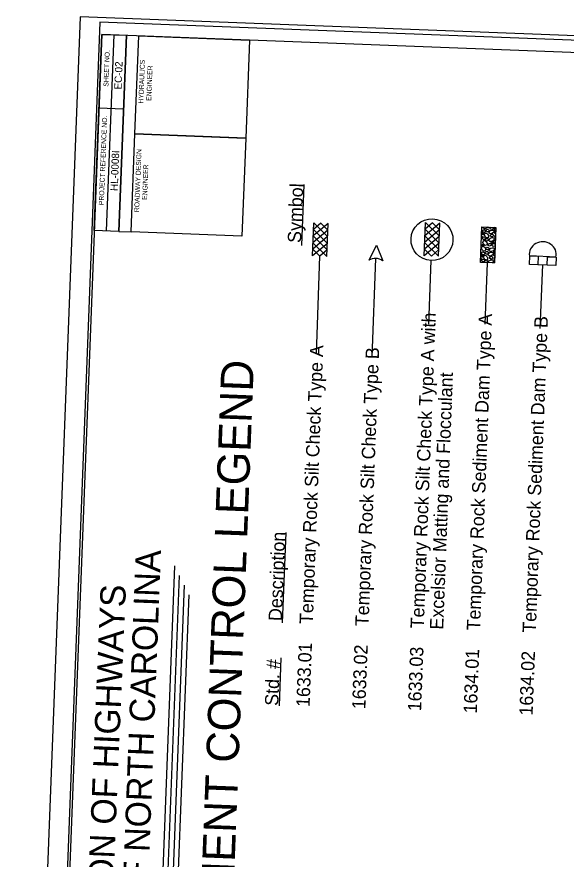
# Model space of a CAD drawing. Extents: x 2094746 to 2100565, y 682095 to 690719.
# Drawn here: x 2094746 to 2097546, y 686425 to 690719 of the extents above; entities that cross this region are included whole.
import ezdxf

# ---------------------------------------------------------------- set-up
doc = ezdxf.new("R2010")
doc.units = 0
for name, color, linetype in [('Default', 7, 'Continuous'), ('Sheet Cutting Line CELL', 7, 'Continuous'), ('Sheet Data Field CELL', 7, 'Continuous'), ('Sheet Plot Border Inside CELL', 7, 'Continuous'), ('Sheet Plot Border Outside CELL', 7, 'Continuous'), ('Sheet Title Data Points CELL', 7, 'Continuous')]:
    doc.layers.add(name, color=color, linetype=linetype)

msp = doc.modelspace()

# ---------------------------------------------------------------- linework, layer by layer
at = {"layer": 'Default'}
for p, q in [((2095471, 685815.7), (2095551.8, 687920.7)), ((2095498.7, 685860.8), (2095575.8, 687871.5)), ((2095527.7, 685905.8), (2095601.3, 687822.3)), ((2095554.1, 685953), (2095623.9, 687773.2))]:
    msp.add_line(p, q, dxfattribs=at)
at = {"layer": 'Sheet Data Field CELL'}
for p, q in [((2095069.1, 690719.1), (2095069.1, 690719.1)), ((2096198.7, 689553.7), (2096210.5, 689864.8)), ((2096252.9, 689500.1), (2096259.3, 689668.8)), ((2096333.1, 689666), (2096256.8, 689602)), ((2096296.2, 689667.4), (2096258, 689634.8)), ((2096259.3, 689668.8), (2096330.4, 689599.2)), ((2096296.2, 689667.4), (2096331.7, 689632)), ((2096326.6, 689497.4), (2096333.1, 689666)), ((2096822.3, 689501.4), (2096828.8, 689670)), ((2096902.4, 689667.3), (2096826.2, 689603.3)), ((2096865.6, 689668.7), (2096827.4, 689636.1)), ((2096828.7, 689670.1), (2096899.8, 689600.5)), ((2096865.6, 689668.7), (2096901.1, 689633.3)), ((2096896, 689498.6), (2096902.4, 689667.3)), ((2096331.7, 689632), (2096255.4, 689566.8)), ((2096258, 689634.8), (2096329.1, 689563.9)), ((2096901.1, 689633.3), (2096824.8, 689568.1)), ((2096827.4, 689636.1), (2096898.5, 689565.2)), ((2096329.1, 689563.9), (2096252.9, 689500.1)), ((2096330.4, 689599.2), (2096254.2, 689534)), ((2096255.4, 689566.8), (2096326.6, 689497.4)), ((2096256.8, 689602), (2096327.9, 689531.3)), ((2096898.5, 689565.2), (2096822.3, 689501.4)), ((2096899.8, 689600.5), (2096823.6, 689535.3)), ((2096824.8, 689568.1), (2096896, 689498.6)), ((2096826.2, 689603.3), (2096897.3, 689532.6)), ((2096254.2, 689534), (2096289.8, 689498.6)), ((2096327.9, 689531.3), (2096289.8, 689498.6)), ((2096541.3, 689478.4), (2096579.8, 689555.5)), ((2096579.8, 689555.5), (2096612.1, 689475.7)), ((2096823.6, 689535.3), (2096859.2, 689499.9)), ((2096897.3, 689532.6), (2096859.2, 689499.9)), ((2096273.4, 689000.2), (2096289.8, 689498.6)), ((2096557.4, 688984.5), (2096576.3, 689487.6)), ((2097495.6, 689494.9), (2097360.9, 689500.1)), ((2097495.6, 689494.9), (2097360.9, 689500.1)), ((2097495.6, 689494.9), (2097493.9, 689451.7)), ((2097495.6, 689494.9), (2097493.9, 689451.7)), ((2096845.8, 689152.9), (2096858.2, 689476.8)), ((2097133.1, 689152.9), (2097144.7, 689465.8)), ((2097493.9, 689451.7), (2097359.3, 689456.9)), ((2097493.9, 689451.7), (2097359.3, 689456.9)), ((2097414.6, 689130.4), (2097426.6, 689454.3)), ((2096100.9, 687629.9), (2096118.5, 688090.3)), ((2096084.6, 687207.1), (2096093.8, 687452.1))]:
    msp.add_line(p, q, dxfattribs=at)
for points in [[(2097109.2, 689466.5), (2097116.2, 689648.4), (2097187.2, 689645.7), (2097180.2, 689465.1)], [(2097109.2, 689466.5), (2097116.2, 689648.4), (2097187.2, 689645.7), (2097180.2, 689465.1)], [(2097359.3, 689456.9), (2097360.9, 689500.1), (2097403.5, 689498.4), (2097401.7, 689455.3)], [(2097449.9, 689453.4), (2097451.6, 689496.6), (2097495.6, 689494.9), (2097493.9, 689451.7)]]:
    msp.add_lwpolyline(points, close=True, dxfattribs=at)
for points in [[(2097115.3, 689622.1), (2097118, 689620.8), (2097117.7, 689614.3), (2097114.8, 689613)], [(2097115.3, 689622.1), (2097118, 689620.8), (2097117.7, 689614.3), (2097114.8, 689613)], [(2097126.5, 689619), (2097121, 689623.2), (2097119.9, 689629.9), (2097124.2, 689633.6), (2097131.3, 689633.3), (2097134, 689629.3), (2097133.7, 689622.9), (2097130.8, 689620.3), (2097126.5, 689619)], [(2097126.5, 689619), (2097121, 689623.2), (2097119.9, 689629.9), (2097124.2, 689633.6), (2097131.3, 689633.3), (2097134, 689629.3), (2097133.7, 689622.9), (2097130.8, 689620.3), (2097126.5, 689619)], [(2097123.2, 689607.5), (2097120.4, 689608.9), (2097120.7, 689612.9), (2097123.5, 689615.4), (2097127.8, 689615.1), (2097129, 689612.5), (2097128.9, 689608.6), (2097127.4, 689607.4), (2097123.2, 689607.5)], [(2097123.2, 689607.5), (2097120.4, 689608.9), (2097120.7, 689612.9), (2097123.5, 689615.4), (2097127.8, 689615.1), (2097129, 689612.5), (2097128.9, 689608.6), (2097127.4, 689607.4), (2097123.2, 689607.5)], [(2097121.8, 689645.4), (2097121.8, 689648.2)], [(2097121.8, 689645.4), (2097121.8, 689648.2)], [(2097138.9, 689647.4), (2097138.7, 689642.2), (2097135.7, 689638.4), (2097130, 689638.6), (2097124.4, 689641.4), (2097121.8, 689645.4)], [(2097138.9, 689647.4), (2097138.7, 689642.2), (2097135.7, 689638.4), (2097130, 689638.6), (2097124.4, 689641.4), (2097121.8, 689645.4)], [(2097132.8, 689599.3), (2097130.3, 689607.3), (2097130.4, 689613.8), (2097134.8, 689616.2), (2097140.5, 689615.9), (2097146, 689611.8), (2097150, 689603.8), (2097149.8, 689597.3), (2097146.7, 689592.1), (2097141, 689592.4), (2097135.5, 689595.2), (2097132.8, 689599.3)], [(2097132.8, 689599.3), (2097130.3, 689607.3), (2097130.4, 689613.8), (2097134.8, 689616.2), (2097140.5, 689615.9), (2097146, 689611.8), (2097150, 689603.8), (2097149.8, 689597.3), (2097146.7, 689592.1), (2097141, 689592.4), (2097135.5, 689595.2), (2097132.8, 689599.3)], [(2097143.6, 689622.4), (2097138.1, 689626.5), (2097138.3, 689633.1), (2097142.8, 689636.9), (2097149.7, 689635.3), (2097152.6, 689632.5), (2097152.3, 689625.9), (2097149.3, 689623.5), (2097143.6, 689622.4)], [(2097143.6, 689622.4), (2097138.1, 689626.5), (2097138.3, 689633.1), (2097142.8, 689636.9), (2097149.7, 689635.3), (2097152.6, 689632.5), (2097152.3, 689625.9), (2097149.3, 689623.5), (2097143.6, 689622.4)], [(2097147.2, 689643.2), (2097141.7, 689647.3)], [(2097147.2, 689643.2), (2097141.7, 689647.3)], [(2097156, 689646.9), (2097156, 689646.9), (2097153, 689644.2), (2097147.2, 689643.2)], [(2097156, 689646.9), (2097156, 689646.9), (2097153, 689644.2), (2097147.2, 689643.2)], [(2097160.9, 689629.5), (2097168, 689631.9), (2097175.3, 689631.6), (2097179.4, 689628.9), (2097177.6, 689623.7), (2097173.3, 689617.3), (2097166, 689613.6), (2097157.5, 689614), (2097153.4, 689616.8), (2097153.6, 689622), (2097156.6, 689627.1), (2097160.9, 689629.5)], [(2097160.9, 689629.5), (2097168, 689631.9), (2097175.3, 689631.6), (2097179.4, 689628.9), (2097177.6, 689623.7), (2097173.3, 689617.3), (2097166, 689613.6), (2097157.5, 689614), (2097153.4, 689616.8), (2097153.6, 689622), (2097156.6, 689627.1), (2097160.9, 689629.5)], [(2097184.3, 689645.8), (2097184.3, 689645.8), (2097178.4, 689639.4), (2097169.7, 689635.9), (2097162.7, 689637.3), (2097158.5, 689640.1), (2097158.7, 689645.4), (2097160.1, 689646.7)], [(2097184.3, 689645.8), (2097184.3, 689645.8), (2097178.4, 689639.4), (2097169.7, 689635.9), (2097162.7, 689637.3), (2097158.5, 689640.1), (2097158.7, 689645.4), (2097160.1, 689646.7)], [(2097166.8, 689597.9), (2097161.3, 689600.7), (2097160.1, 689607.4), (2097165.9, 689611.1), (2097171.5, 689610.9), (2097175.7, 689606.7), (2097174.1, 689601.7), (2097171.1, 689597.8), (2097166.8, 689597.9)], [(2097166.8, 689597.9), (2097161.3, 689600.7), (2097160.1, 689607.4), (2097165.9, 689611.1), (2097171.5, 689610.9), (2097175.7, 689606.7), (2097174.1, 689601.7), (2097171.1, 689597.8), (2097166.8, 689597.9)], [(2097185.8, 689613), (2097181.6, 689615.8), (2097180.5, 689622.3), (2097184.9, 689626.2), (2097186.3, 689626.1)], [(2097185.8, 689613), (2097181.6, 689615.8), (2097180.5, 689622.3), (2097184.9, 689626.2), (2097186.3, 689626.1)], [(2097186.4, 689628.7), (2097182.3, 689631.4), (2097181.1, 689638), (2097186.9, 689641.7), (2097186.9, 689641.7)], [(2097186.4, 689628.7), (2097182.3, 689631.4), (2097181.1, 689638), (2097186.9, 689641.7), (2097186.9, 689641.7)], [(2097114.5, 689602.6), (2097117.3, 689599.8), (2097116.9, 689593.3), (2097114.1, 689592.1)], [(2097114.5, 689602.6), (2097117.3, 689599.8), (2097116.9, 689593.3), (2097114.1, 689592.1)], [(2097125.2, 689583.8), (2097119.6, 689587.9), (2097119.8, 689593.1), (2097124.2, 689598.3), (2097131.3, 689596.6), (2097134, 689592.7), (2097133.8, 689587.4), (2097130.8, 689584.8), (2097125.2, 689583.8)], [(2097125.2, 689583.8), (2097119.6, 689587.9), (2097119.8, 689593.1), (2097124.2, 689598.3), (2097131.3, 689596.6), (2097134, 689592.7), (2097133.8, 689587.4), (2097130.8, 689584.8), (2097125.2, 689583.8)], [(2097124.3, 689560.2), (2097121.6, 689568.2), (2097123.4, 689574.7), (2097126.3, 689578.6), (2097131.9, 689578.3), (2097138.9, 689572.8), (2097142.8, 689564.9), (2097142.6, 689558.2), (2097139.6, 689554.4), (2097133.8, 689553.4), (2097128.4, 689557.5), (2097124.3, 689561.5)], [(2097124.3, 689560.2), (2097121.6, 689568.2), (2097123.4, 689574.7), (2097126.3, 689578.6), (2097131.9, 689578.3), (2097138.9, 689572.8), (2097142.8, 689564.9), (2097142.6, 689558.2), (2097139.6, 689554.4), (2097133.8, 689553.4), (2097128.4, 689557.5), (2097124.3, 689561.5)], [(2097140.4, 689575.3), (2097135, 689580.9), (2097135.1, 689586.1), (2097139.5, 689589.8), (2097146.6, 689589.5), (2097149.3, 689585.4), (2097149.1, 689579.1), (2097146.1, 689576.5), (2097140.4, 689575.3)], [(2097140.4, 689575.3), (2097135, 689580.9), (2097135.1, 689586.1), (2097139.5, 689589.8), (2097146.6, 689589.5), (2097149.3, 689585.4), (2097149.1, 689579.1), (2097146.1, 689576.5), (2097140.4, 689575.3)], [(2097155, 689549.8), (2097149.4, 689554), (2097148.4, 689560.7), (2097154.1, 689564.3), (2097159.8, 689564.1), (2097164, 689560), (2097162.3, 689553.5), (2097159.4, 689551.1), (2097155, 689549.8)], [(2097155, 689549.8), (2097149.4, 689554), (2097148.4, 689560.7), (2097154.1, 689564.3), (2097159.8, 689564.1), (2097164, 689560), (2097162.3, 689553.5), (2097159.4, 689551.1), (2097155, 689549.8)], [(2097160.9, 689591.6), (2097168.1, 689593.9), (2097175.1, 689592.4), (2097179.2, 689589.6), (2097179.1, 689584.4), (2097173.2, 689578.1), (2097164.5, 689574.4), (2097157.4, 689574.7), (2097153.2, 689577.5), (2097153.4, 689582.7), (2097156.5, 689587.9), (2097160.9, 689590.3)], [(2097160.9, 689591.6), (2097168.1, 689593.9), (2097175.1, 689592.4), (2097179.2, 689589.6), (2097179.1, 689584.4), (2097173.2, 689578.1), (2097164.5, 689574.4), (2097157.4, 689574.7), (2097153.2, 689577.5), (2097153.4, 689582.7), (2097156.5, 689587.9), (2097160.9, 689590.3)], [(2097166.9, 689562.6), (2097164.1, 689565.4), (2097164.3, 689569.2), (2097165.8, 689571.7), (2097170.1, 689571.6), (2097172.8, 689568.8), (2097172.7, 689564.9), (2097169.8, 689563.8), (2097166.9, 689562.6)], [(2097166.9, 689562.6), (2097164.1, 689565.4), (2097164.3, 689569.2), (2097165.8, 689571.7), (2097170.1, 689571.6), (2097172.8, 689568.8), (2097172.7, 689564.9), (2097169.8, 689563.8), (2097166.9, 689562.6)], [(2097174.9, 689549.2), (2097169.4, 689553.3), (2097169.6, 689558.5), (2097174, 689563.7), (2097181, 689562.1), (2097183.8, 689558.1)], [(2097174.9, 689549.2), (2097169.4, 689553.3), (2097169.6, 689558.5), (2097174, 689563.7), (2097181, 689562.1), (2097183.8, 689558.1)], [(2097182.4, 689564.6), (2097175.6, 689568.8), (2097175.9, 689575.2), (2097180.2, 689579.1), (2097184.5, 689579)], [(2097182.4, 689564.6), (2097175.6, 689568.8), (2097175.9, 689575.2), (2097180.2, 689579.1), (2097184.5, 689579)], [(2097185.2, 689593.2), (2097182.4, 689597.4), (2097184.1, 689605.1), (2097185.4, 689605)], [(2097185.2, 689593.2), (2097182.4, 689597.4), (2097184.1, 689605.1), (2097185.4, 689605)], [(2097184, 689564.4), (2097182.4, 689564.6)], [(2097184, 689564.4), (2097182.4, 689564.6)], [(2097112.3, 689543.7), (2097113.6, 689543.7), (2097113.3, 689537.1), (2097112, 689537.1)], [(2097112.3, 689543.7), (2097113.6, 689543.7), (2097113.3, 689537.1), (2097112, 689537.1)], [(2097117.5, 689533.1), (2097114.9, 689539.6), (2097115.2, 689546.2), (2097119.5, 689548.6), (2097125.2, 689548.4), (2097132.1, 689544.2), (2097134.6, 689536.3), (2097134.4, 689529.8), (2097131.4, 689526), (2097125.7, 689524.8), (2097120.2, 689528.9), (2097117.5, 689533.1)], [(2097117.5, 689533.1), (2097114.9, 689539.6), (2097115.2, 689546.2), (2097119.5, 689548.6), (2097125.2, 689548.4), (2097132.1, 689544.2), (2097134.6, 689536.3), (2097134.4, 689529.8), (2097131.4, 689526), (2097125.7, 689524.8), (2097120.2, 689528.9), (2097117.5, 689533.1)], [(2097122.2, 689506.5), (2097116.6, 689510.8), (2097115.5, 689517.3), (2097119.9, 689521.2), (2097126.9, 689519.5), (2097131.1, 689515.5), (2097129.3, 689510.2), (2097126.4, 689506.5), (2097122.2, 689506.5)], [(2097122.2, 689506.5), (2097116.6, 689510.8), (2097115.5, 689517.3), (2097119.9, 689521.2), (2097126.9, 689519.5), (2097131.1, 689515.5), (2097129.3, 689510.2), (2097126.4, 689506.5), (2097122.2, 689506.5)], [(2097121.1, 689551.1), (2097117, 689554), (2097117, 689556.7), (2097120, 689559.1), (2097124.2, 689559), (2097125.5, 689556.3), (2097125.3, 689552.3), (2097123.8, 689551.1), (2097121.1, 689551.1)], [(2097121.1, 689551.1), (2097117, 689554), (2097117, 689556.7), (2097120, 689559.1), (2097124.2, 689559), (2097125.5, 689556.3), (2097125.3, 689552.3), (2097123.8, 689551.1), (2097121.1, 689551.1)], [(2097139.3, 689510), (2097133.9, 689514), (2097134.1, 689519.2), (2097138.3, 689523), (2097145.5, 689522.8), (2097148.1, 689518.8), (2097148, 689513.5), (2097145.1, 689509.6), (2097139.3, 689510)], [(2097139.3, 689510), (2097133.9, 689514), (2097134.1, 689519.2), (2097138.3, 689523), (2097145.5, 689522.8), (2097148.1, 689518.8), (2097148, 689513.5), (2097145.1, 689509.6), (2097139.3, 689510)], [(2097144.4, 689530.7), (2097137.3, 689533.6), (2097137.6, 689540.2), (2097143.5, 689545.2), (2097149, 689543.6), (2097153.3, 689539.5), (2097151.6, 689534.3), (2097148.6, 689530.6), (2097144.4, 689530.7)], [(2097144.4, 689530.7), (2097137.3, 689533.6), (2097137.6, 689540.2), (2097143.5, 689545.2), (2097149, 689543.6), (2097153.3, 689539.5), (2097151.6, 689534.3), (2097148.6, 689530.6), (2097144.4, 689530.7)], [(2097161.7, 689539.2), (2097168.8, 689541.5), (2097176, 689541.3), (2097180.2, 689538.5), (2097179.8, 689532), (2097174, 689526.9), (2097165.4, 689523.2), (2097158.2, 689523.6), (2097154.1, 689526.3), (2097154.3, 689531.5), (2097157.4, 689536.7), (2097161.7, 689539.2)], [(2097161.7, 689539.2), (2097168.8, 689541.5), (2097176, 689541.3), (2097180.2, 689538.5), (2097179.8, 689532), (2097174, 689526.9), (2097165.4, 689523.2), (2097158.2, 689523.6), (2097154.1, 689526.3), (2097154.3, 689531.5), (2097157.4, 689536.7), (2097161.7, 689539.2)], [(2097183.5, 689552.7), (2097183.5, 689551.4), (2097180.6, 689550.2), (2097174.9, 689549.2)], [(2097183.5, 689552.7), (2097183.5, 689551.4), (2097180.6, 689550.2), (2097174.9, 689549.2)], [(2097182, 689514.7), (2097178, 689519), (2097176.8, 689525.5), (2097182.6, 689529.2), (2097182.6, 689529.2)], [(2097182, 689514.7), (2097178, 689519), (2097176.8, 689525.5), (2097182.6, 689529.2), (2097182.6, 689529.2)], [(2097182.8, 689534.4), (2097181.5, 689534.5), (2097181.5, 689538.5), (2097183, 689539.7)], [(2097182.8, 689534.4), (2097181.5, 689534.5), (2097181.5, 689538.5), (2097183, 689539.7)], [(2097110.2, 689488.7), (2097113, 689487.3), (2097112.6, 689480.8), (2097109.8, 689479.7)], [(2097110.2, 689488.7), (2097113, 689487.3), (2097112.6, 689480.8), (2097109.8, 689479.7)], [(2097110.8, 689508.4), (2097113.7, 689507), (2097113.4, 689500.4), (2097110.6, 689499.2)], [(2097110.8, 689508.4), (2097113.7, 689507), (2097113.4, 689500.4), (2097110.6, 689499.2)], [(2097120.7, 689470), (2097115.3, 689475.4), (2097115.5, 689480.6), (2097119.9, 689484.6), (2097127, 689484.1), (2097129.6, 689480.1), (2097129.3, 689473.5), (2097126.5, 689471.2), (2097120.7, 689470)], [(2097120.7, 689470), (2097115.3, 689475.4), (2097115.5, 689480.6), (2097119.9, 689484.6), (2097127, 689484.1), (2097129.6, 689480.1), (2097129.3, 689473.5), (2097126.5, 689471.2), (2097120.7, 689470)], [(2097118.7, 689493.6), (2097116.1, 689496.4), (2097116.2, 689500.2), (2097119.2, 689502.9), (2097123.5, 689502.6), (2097124.8, 689498.8), (2097124.6, 689496), (2097123, 689493.5), (2097118.7, 689493.6)], [(2097118.7, 689493.6), (2097116.1, 689496.4), (2097116.2, 689500.2), (2097119.2, 689502.9), (2097123.5, 689502.6), (2097124.8, 689498.8), (2097124.6, 689496), (2097123, 689493.5), (2097118.7, 689493.6)], [(2097128.4, 689486.7), (2097125.8, 689493.3), (2097126.2, 689500), (2097130.6, 689503.7), (2097136.2, 689503.4), (2097141.7, 689497.9), (2097145.6, 689490), (2097145.4, 689483.4), (2097142.5, 689479.6), (2097136.7, 689479.9), (2097131.2, 689482.6), (2097128.4, 689486.7)], [(2097128.4, 689486.7), (2097125.8, 689493.3), (2097126.2, 689500), (2097130.6, 689503.7), (2097136.2, 689503.4), (2097141.7, 689497.9), (2097145.6, 689490), (2097145.4, 689483.4), (2097142.5, 689479.6), (2097136.7, 689479.9), (2097131.2, 689482.6), (2097128.4, 689486.7)], [(2097130.5, 689467.1), (2097130.5, 689467.1), (2097130.7, 689472.2), (2097135.1, 689477.4), (2097142.3, 689475.7), (2097144.9, 689471.7), (2097144.7, 689466.5), (2097144.7, 689466.5)], [(2097130.5, 689467.1), (2097130.5, 689467.1), (2097130.7, 689472.2), (2097135.1, 689477.4), (2097142.3, 689475.7), (2097144.9, 689471.7), (2097144.7, 689466.5), (2097144.7, 689466.5)], [(2097148.9, 689465), (2097149.1, 689470.2), (2097152.1, 689475.3), (2097156.5, 689477.8)], [(2097148.9, 689465), (2097149.1, 689470.2), (2097152.1, 689475.3), (2097156.5, 689477.8)], [(2097156.6, 689517.1), (2097165.1, 689519.4), (2097170.8, 689517.8), (2097175, 689515.1), (2097173.4, 689510), (2097168.9, 689504.8), (2097161.7, 689499.8), (2097153.2, 689501.6), (2097149, 689504.3), (2097149.2, 689509.5), (2097152.2, 689513.3), (2097156.6, 689517.1)], [(2097156.6, 689517.1), (2097165.1, 689519.4), (2097170.8, 689517.8), (2097175, 689515.1), (2097173.4, 689510), (2097168.9, 689504.8), (2097161.7, 689499.8), (2097153.2, 689501.6), (2097149, 689504.3), (2097149.2, 689509.5), (2097152.2, 689513.3), (2097156.6, 689517.1)], [(2097162.4, 689484.1), (2097155.5, 689488.2), (2097155.8, 689494.8), (2097161.6, 689498.5), (2097167.2, 689497.1), (2097171.2, 689494.3), (2097169.7, 689487.7), (2097166.7, 689485.3), (2097162.4, 689484.1)], [(2097162.4, 689484.1), (2097155.5, 689488.2), (2097155.8, 689494.8), (2097161.6, 689498.5), (2097167.2, 689497.1), (2097171.2, 689494.3), (2097169.7, 689487.7), (2097166.7, 689485.3), (2097162.4, 689484.1)], [(2097156.5, 689477.8), (2097163.8, 689480.1), (2097170.8, 689479.9), (2097173.4, 689477.1), (2097174.7, 689470.6), (2097168.6, 689464.3)], [(2097156.5, 689477.8), (2097163.8, 689480.1), (2097170.8, 689479.9), (2097173.4, 689477.1), (2097174.7, 689470.6), (2097168.6, 689464.3)], [(2097181.4, 689499.1), (2097177.4, 689503.2), (2097176.2, 689509.8), (2097180.6, 689513.6), (2097182, 689513.4)], [(2097181.4, 689499.1), (2097177.4, 689503.2), (2097176.2, 689509.8), (2097180.6, 689513.6), (2097182, 689513.4)], [(2097180.7, 689480.7), (2097179.5, 689484.8), (2097179.7, 689491.3), (2097181.2, 689492.5)], [(2097180.7, 689480.7), (2097179.5, 689484.8), (2097179.7, 689491.3), (2097181.2, 689492.5)], [(2097174.5, 689465.4), (2097176, 689466.6), (2097180.2, 689465.1)], [(2097174.5, 689465.4), (2097176, 689466.6), (2097180.2, 689465.1)]]:
    msp.add_lwpolyline(points, dxfattribs=at)
msp.add_ellipse((2096862.3, 689583.3), major_axis=(-106.9, 4.1), ratio=0.995697, dxfattribs=at)
for centre, major_axis, start_param, end_param in [((2097427.2, 689509.2), (-68.6, 2.6), 2.949905, 6.474869), ((2097427.2, 689509.2), (-68.6, 2.6), 2.949905, 6.474869), ((2096574.2, 689432.8), (59.3, -2.3), 0.944994, 2.196599)]:
    msp.add_ellipse(centre, major_axis=major_axis, ratio=0.923408, start_param=start_param, end_param=end_param, dxfattribs=at)
at = {"layer": 'Sheet Plot Border Inside CELL'}
msp.add_lwpolyline([(2100242.3, 682094.5), (2100565.2, 690508.1), (2095069.1, 690719.1), (2094746.1, 682305.5)], close=True, dxfattribs=at)
at = {"layer": 'Sheet Plot Border Outside CELL'}
msp.add_lwpolyline([(2100144.4, 682163.3), (2100464, 690489.5), (2095168.6, 690692.8), (2094849, 682366.6)], close=True, dxfattribs=at)
at = {"layer": 'Sheet Title Data Points CELL'}
for p, q in [((2095203.4, 689627.6), (2095241.7, 690627.4)), ((2095266.1, 689625.2), (2095304.5, 690625)), ((2095164.6, 690255), (2095290.1, 690250.1)), ((2095348, 690122.8), (2095912.5, 690101.1)), ((2095266.1, 689625.2), (2095328.8, 689622.8))]:
    msp.add_line(p, q, dxfattribs=at)
for points in [[(2095178.7, 690629.8), (2094891, 683133.2), (2100161.3, 682931), (2100449, 690427.5)], [(2095140.4, 689630), (2095178.7, 690629.8), (2095304.5, 690625), (2095266.1, 689625.2)], [(2095348, 690122.8), (2095367.2, 690622.6), (2095931.9, 690600.9), (2095912.7, 690101.1)], [(2095328.8, 689622.8), (2095348, 690122.8), (2095912.7, 690101.1), (2095893.5, 689601.1)]]:
    msp.add_lwpolyline(points, close=True, dxfattribs=at)

# ---------------------------------------------------------------- texts
at = {"layer": 'Default'}
for s, height, p in [('EROSION & SEDIMENT CONTROL LEGEND', 165.585, (2095780.4, 684418.3)), ('STATE OF NORTH CAROLINA', 128.788, (2095387.9, 685571.4))]:
    msp.add_text(s, height=height, rotation=87.802, dxfattribs=at).set_placement(p)
at = {"layer": 'Sheet Cutting Line CELL'}
msp.add_text(' DIVISION OF HIGHWAYS', height=128.788, rotation=87.5709, dxfattribs=at).set_placement((2095214.8, 685748.2))
at = {"layer": 'Sheet Data Field CELL'}
for s, height, p in [('Symbol', 68.14, (2096194.8, 689565.6)), ('Temporary Rock Silt Check Type A with', 68.14, (2096820.3, 687601.1)), ('Temporary Rock Sediment Dam Type A', 68.167, (2097107.2, 687590.1)), ('Temporary Rock Sediment Dam Type B', 68.14, (2097391.4, 687578.6)), ('Temporary Rock Silt Check Type A', 68.14, (2096254.6, 687622.8)), ('Temporary Rock Silt Check Type B', 68.14, (2096538.8, 687611.9)), ('Excelsior Matting and Flocculant', 68.14, (2096919.4, 687594.6)), ('Description', 68.14, (2096096.9, 687638)), ('1633.01', 68.05, (2096238.3, 687200)), ('1633.02', 68.05, (2096522.5, 687189.1)), ('1633.03', 68.05, (2096806.7, 687178.2)), ('1634.01', 68.05, (2097090.9, 687167.3)), ('1634.02', 68.05, (2097375.1, 687156.4)), ('Std. #', 68.14, (2096078.5, 687206.1))]:
    msp.add_text(s, height=height, rotation=87.802, dxfattribs=at).set_placement(p)
at = {"layer": 'Sheet Title Data Points CELL'}
for s, height, p in [('SHEET NO.', 25.12, (2095212.7, 690362.7)), ('EC-02', 37.67, (2095280, 690348.2)), ('HYDRAULICS', 25.12, (2095390.6, 690276.5)), ('ENGINEER', 25.12, (2095431.1, 690290.1)), ('PROJECT REFERENCE NO.', 25.116, (2095189, 689758.9)), ('HL-0008I', 37.67, (2095260.5, 689830.7)), ('ROADWAY DESIGN', 25.116, (2095369.4, 689723)), ('ENGINEER', 25.12, (2095409.7, 689785.6))]:
    msp.add_text(s, height=height, rotation=87.802, dxfattribs=at).set_placement(p)

doc.saveas('drawing.dxf')
